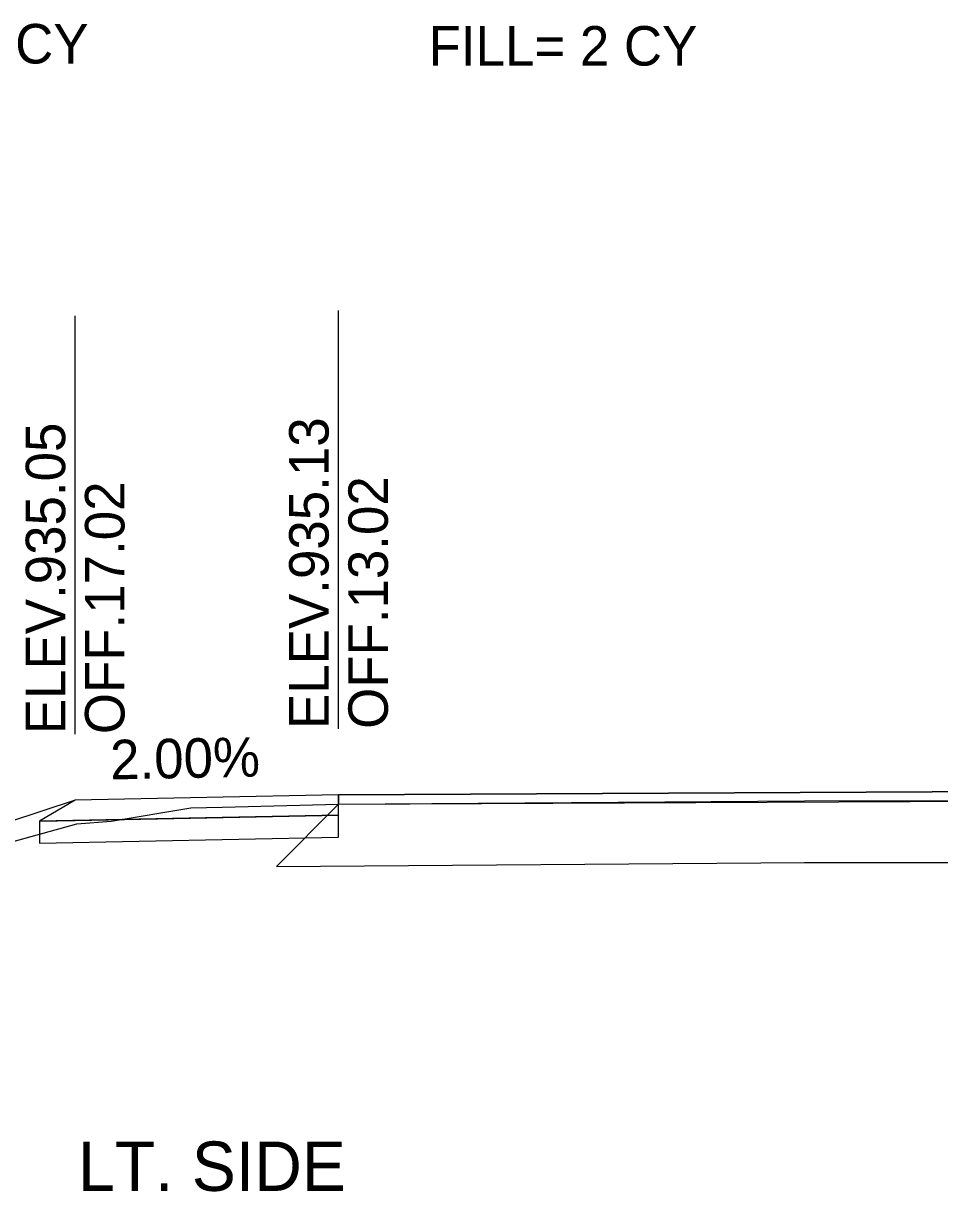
# Model space of a CAD drawing. Extents: x -4 to 359, y 0 to 1436.
# Drawn here: x 234.69 to 248.61, y 924.08 to 941.81 of the extents above; entities that cross this region are included whole.
import ezdxf

# ---------------------------------------------------------------- set-up
doc = ezdxf.new("R2010")
doc.units = 0
for name, color, linetype in [('XS-Existing subsurface-pavement', 7, 'Continuous'), ('XS-Existing surface-ground', 7, 'Continuous'), ('XS-Proposed Finish Grade', 7, 'Continuous'), ('XS-Proposed subsurface-aggregate layer 1', 7, 'Continuous'), ('XS-Proposed surface-ground', 7, 'Continuous'), ('XS-Proposed surface-pavement', 7, 'Continuous'), ('XS-Proposed surface-shoulder', 7, 'Continuous'), ('XS-Text-earthwork labels', 7, 'Continuous'), ('XS-Text-pavement elevation', 7, 'Continuous'), ('XS-Text-profile report', 7, 'Continuous'), ('XS-Text-shoulder slope', 7, 'Continuous'), ('XS-Text-tie offset', 7, 'Continuous')]:
    doc.layers.add(name, color=color, linetype=linetype)

msp = doc.modelspace()

# ---------------------------------------------------------------- linework, layer by layer
at = {"layer": 'XS-Existing subsurface-pavement'}
for p, q in [((239.478, 929.959), (238.534, 929.014)), ((238.534, 929.014), (246.56, 929.073)), ((246.555, 929.073), (252.502, 929.083))]:
    msp.add_line(p, q, dxfattribs=at)
at = {"layer": 'XS-Existing surface-ground'}
for p, q in [((239.478, 929.959), (246.553, 930.01)), ((246.553, 930.01), (252.5, 930.02)), ((236.024, 929.702), (237.237, 929.907)), ((237.237, 929.907), (237.709, 929.915)), ((237.709, 929.915), (239.478, 929.959)), ((233.596, 929.131), (235.503, 929.661)), ((235.503, 929.661), (236.024, 929.702))]:
    msp.add_line(p, q, dxfattribs=at)
at = {"layer": 'XS-Proposed Finish Grade'}
for points in [[(239.478, 930.104), (252.5, 930.166), (262.582, 930.183)], [(239.478, 930.104), (235.478, 930.024)]]:
    msp.add_lwpolyline(points, dxfattribs=at)
at = {"layer": 'XS-Proposed subsurface-aggregate layer 1'}
for points in [[(239.478, 929.792), (234.939, 929.701)], [(234.939, 929.701), (234.939, 929.368)], [(239.478, 929.459), (239.478, 929.792)], [(234.939, 929.368), (239.478, 929.459)]]:
    msp.add_lwpolyline(points, dxfattribs=at)
at = {"layer": 'XS-Proposed surface-ground'}
msp.add_lwpolyline([(235.478, 930.024), (228.405, 927.69)], dxfattribs=at)
at = {"layer": 'XS-Proposed surface-pavement'}
for points in [[(262.582, 930.183), (252.5, 930.166), (239.478, 930.104)], [(239.478, 930.104), (239.478, 929.959)], [(239.478, 929.959), (252.5, 930.02), (262.582, 930.037)]]:
    msp.add_lwpolyline(points, dxfattribs=at)
at = {"layer": 'XS-Proposed surface-shoulder'}
for points in [[(239.478, 930.104), (235.478, 930.024), (234.939, 929.701)], [(239.478, 929.792), (239.478, 930.104)], [(234.939, 929.701), (235.478, 929.712), (239.478, 929.792)]]:
    msp.add_lwpolyline(points, dxfattribs=at)
at = {"layer": 'XS-Text-tie offset'}
for p, q in [((239.478, 931.104), (239.478, 937.454)), ((235.478, 931.024), (235.478, 937.376))]:
    msp.add_line(p, q, dxfattribs=at)

# ---------------------------------------------------------------- texts
at = {"layer": 'XS-Text-earthwork labels'}
for s, height, p in [(' CUT= 3 CY           ', 0.6, (231.335, 941.204)), ('FILL= 2 CY           ', 0.6, (240.846, 941.172)), ('LT. SIDE', 0.75, (235.522, 924.09))]:
    msp.add_text(s, height=height, dxfattribs=at).set_placement(p)
at = {"layer": 'XS-Text-pavement elevation'}
for s, p in [('ELEV.935.05', (235.328, 931.024)), ('ELEV.935.13', (239.328, 931.104)), ('OFF.17.02', (236.228, 931.024)), ('OFF.13.02', (240.228, 931.104))]:
    msp.add_text(s, height=0.6, rotation=90, dxfattribs=at).set_placement(p)
at = {"layer": 'XS-Text-profile report'}
for s, p in [('Shldr_Surf_Asph_T1', (235.464, 930.024)), ('Pvmt_Surf_Asph_T2_L', (239.463, 930.104)), ('Pvmt_Surf_Asph_T_L', (239.464, 929.958)), ('Shldr_Surf_Asph_B2', (234.925, 929.7)), ('Shldr_Surf_Asph_B1', (235.464, 929.711)), ('Shldr_Surf_Asph_B12', (239.463, 929.791)), ('Agg_Layer_1_B', (239.468, 929.458)), ('Agg_Layer_1_B1', (234.928, 929.367))]:
    msp.add_text(s, height=0.00167, dxfattribs=at).set_placement(p)
at = {"layer": 'XS-Text-shoulder slope'}
msp.add_text('2.00%', height=0.6, rotation=1.1458, dxfattribs=at).set_placement((236.016, 930.335))

doc.saveas('drawing.dxf')
